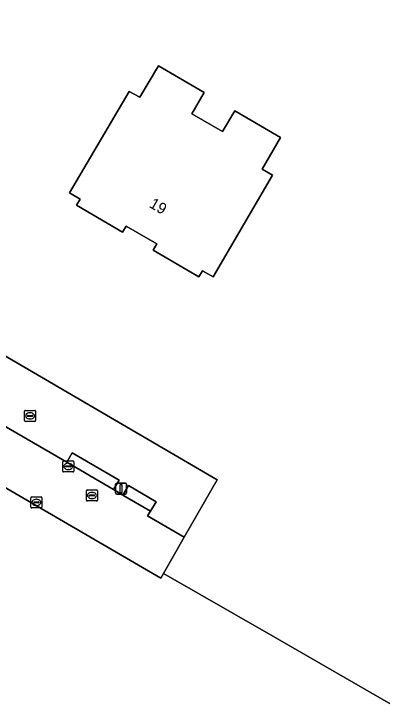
# Model space of a CAD drawing. Extents: x 156502 to 159075, y 384229 to 386100.
# Drawn here: x 157237.2 to 157270.5, y 385820 to 385882.9 of the extents above; entities that cross this region are included whole.
import ezdxf

# ---------------------------------------------------------------- set-up
doc = ezdxf.new("R2010")
doc.units = 0
for name, color, linetype in [('IMGEO_Erf', 7, 'Continuous'), ('IMGEO_Grasland_overig', 7, 'Continuous'), ('IMGEO_Groenvoorziening', 7, 'Continuous'), ('IMGEO_Haag', 7, 'Continuous'), ('IMGEO_Hek', 7, 'Continuous'), ('IMGEO_Kolk', 7, 'Continuous'), ('IMGEO_Lichtmast', 7, 'Continuous'), ('IMGEO_Pand', 7, 'Continuous'), ('IMGEO_Pand_nummerreeks', 7, 'Continuous'), ('IMGEO_Rijbaan_lokaal_open', 7, 'Continuous'), ('IMGEO_Rioolput', 7, 'Continuous'), ('IMGEO_Voetpad_open', 7, 'Continuous')]:
    doc.layers.add(name, color=color, linetype=linetype)

msp = doc.modelspace()

# ---------------------------------------------------------------- linework, layer by layer
at = {"layer": 'IMGEO_Erf'}
msp.add_lwpolyline([(157242.826, 385865.609), (157243.156, 385866.162), (157242.212, 385866.726), (157247.585, 385875.898), (157248.555, 385875.375), (157250.234, 385878.2), (157254.372, 385875.786), (157253.258, 385873.877), (157256.043, 385872.253), (157257.148, 385874.146), (157261.288, 385871.729), (157259.62, 385868.87), (157260.57, 385868.316), (157255.182, 385859.122), (157254.232, 385859.683), (157253.898, 385859.114), (157249.757, 385861.548), (157250.086, 385862.113), (157247.316, 385863.723), (157246.981, 385863.155)], close=True, dxfattribs=at)
msp.add_lwpolyline([(157226.078, 385857.975), (157255.558, 385840.78), (157252.582, 385835.588), (157250.702, 385832.309), (157260.436, 385826.723), (157272.043, 385820.045)], dxfattribs=at)
at = {"layer": 'IMGEO_Grasland_overig'}
msp.add_lwpolyline([(157272.043, 385820.045), (157260.436, 385826.723), (157250.702, 385832.309), (157250.457, 385831.882), (157205.703, 385857.935)], dxfattribs=at)
at = {"layer": 'IMGEO_Groenvoorziening'}
for points in [[(157242.451, 385843.218), (157241.947, 385842.373), (157246.178, 385839.897), (157246.682, 385840.755)], [(157247.026, 385839.395), (157249.511, 385837.937), (157250.029, 385838.788), (157247.532, 385840.247)]]:
    msp.add_lwpolyline(points, close=True, dxfattribs=at)
at = {"layer": 'IMGEO_Haag'}
for points in [[(157242.451, 385843.218), (157241.947, 385842.373), (157246.178, 385839.897), (157246.682, 385840.755)], [(157247.026, 385839.395), (157249.511, 385837.937), (157250.029, 385838.788), (157247.532, 385840.247)]]:
    msp.add_lwpolyline(points, close=True, dxfattribs=at)
at = {"layer": 'IMGEO_Hek'}
for points in [[(157250.457, 385831.882), (157250.702, 385832.309)], [(157260.436, 385826.723), (157250.702, 385832.309)], [(157260.436, 385826.723), (157272.043, 385820.045)]]:
    msp.add_lwpolyline(points, dxfattribs=at)
at = {"layer": 'IMGEO_Kolk'}
for p, q in [((157241.584, 385841.563), (157241.584, 385842.415)), ((157241.659, 385842.489), (157242.511, 385842.489)), ((157242.585, 385842.415), (157242.585, 385841.563)), ((157241.843, 385841.983), (157241.843, 385841.995)), ((157242.281, 385841.946), (157241.883, 385841.946)), ((157241.886, 385842.032), (157242.284, 385842.032)), ((157242.095, 385841.709), (157242.07, 385841.709)), ((157242.072, 385842.269), (157242.097, 385842.269)), ((157242.327, 385841.995), (157242.327, 385841.983)), ((157242.511, 385841.489), (157241.659, 385841.489)), ((157238.781, 385839.233), (157239.633, 385839.233)), ((157238.706, 385838.307), (157238.706, 385839.159)), ((157238.965, 385838.727), (157238.965, 385838.739)), ((157239.403, 385838.69), (157239.005, 385838.69)), ((157239.008, 385838.776), (157239.406, 385838.776)), ((157239.194, 385839.013), (157239.219, 385839.013)), ((157239.449, 385838.739), (157239.449, 385838.727)), ((157239.707, 385839.159), (157239.707, 385838.307)), ((157239.633, 385838.233), (157238.781, 385838.233)), ((157239.217, 385838.453), (157239.192, 385838.453))]:
    msp.add_line(p, q, dxfattribs=at)
for points in [[(157241.584, 385841.563), (157241.584, 385842.415)], [(157241.659, 385842.489), (157242.511, 385842.489)], [(157242.585, 385842.415), (157242.585, 385841.563)], [(157242.511, 385841.489), (157241.659, 385841.489)], [(157238.781, 385839.233), (157239.633, 385839.233)], [(157238.706, 385838.307), (157238.706, 385839.159)], [(157239.707, 385839.159), (157239.707, 385838.307)], [(157239.633, 385838.233), (157238.781, 385838.233)]]:
    msp.add_lwpolyline(points, dxfattribs=at)
for centre, radius, start, end in [((157241.661, 385842.413), 0.0765, 91.55205, 178.44795), ((157241.661, 385842.413), 0.0765, 91.55205, 178.44795), ((157242.509, 385842.413), 0.0765, 1.55205, 88.44795), ((157242.509, 385842.413), 0.0765, 1.55205, 88.44795), ((157241.883, 385841.992), 0.0403, 85.87752, 175.75265), ((157241.88, 385841.982), 0.0366, 178.93798, 274.71019), ((157242.284, 385841.989), 0.043, 264.86636, 352.45326), ((157242.288, 385841.994), 0.0386, 1.73085, 96.63898), ((157241.661, 385841.565), 0.0765, 181.55205, 268.44795), ((157241.661, 385841.565), 0.0765, 181.55205, 268.44795), ((157242.509, 385841.565), 0.0765, 271.55205, 358.44795), ((157242.509, 385841.565), 0.0765, 271.55205, 358.44795), ((157238.783, 385839.157), 0.0765, 91.55205, 178.44795), ((157238.783, 385839.157), 0.0765, 91.55205, 178.44795), ((157239.631, 385839.157), 0.0765, 1.55205, 88.44795), ((157239.631, 385839.157), 0.0765, 1.55205, 88.44795), ((157239.005, 385838.736), 0.0403, 85.87752, 175.75265), ((157239.002, 385838.726), 0.0366, 178.93798, 274.71019), ((157239.406, 385838.733), 0.043, 264.86636, 352.45326), ((157239.41, 385838.738), 0.0386, 1.73085, 96.63898), ((157238.783, 385838.309), 0.0765, 181.55205, 268.44795), ((157238.783, 385838.309), 0.0765, 181.55205, 268.44795), ((157239.631, 385838.309), 0.0765, 271.55205, 358.44795), ((157239.631, 385838.309), 0.0765, 271.55205, 358.44795)]:
    msp.add_arc(centre, radius, start, end, dxfattribs=at)
for centre, major_axis, ratio, start_param, end_param in [((157242.071, 385841.989), (-0.387, 0.002), 0.722429, 4.712389, 7.853982), ((157242.096, 385841.989), (-0.39, 0.002), 0.717154, 1.570796, 4.712389), ((157239.193, 385838.733), (-0.387, 0.002), 0.722429, 4.712389, 7.853982), ((157239.218, 385838.733), (-0.39, 0.002), 0.717154, 1.570796, 4.712389)]:
    msp.add_ellipse(centre, major_axis=major_axis, ratio=ratio, start_param=start_param, end_param=end_param, dxfattribs=at)
at = {"layer": 'IMGEO_Lichtmast'}
for p, q in [((157246.466, 385840.484), (157247.256, 385840.484)), ((157247.256, 385840.484), (157246.466, 385840.484)), ((157246.366, 385839.584), (157246.366, 385840.384)), ((157246.366, 385840.384), (157246.366, 385839.584)), ((157247.356, 385840.384), (157247.356, 385839.584)), ((157247.356, 385839.584), (157247.356, 385840.384)), ((157247.256, 385839.484), (157246.466, 385839.484)), ((157246.466, 385839.484), (157247.256, 385839.484))]:
    msp.add_line(p, q, dxfattribs=at)
msp.add_lwpolyline([(157246.786, 385840.359), (157246.936, 385840.359), (157246.936, 385839.609), (157246.786, 385839.609), (157246.786, 385840.359)], dxfattribs=at)
for centre, start, end in [((157246.466, 385840.384), 90, 180), ((157246.466, 385840.384), 90, 180), ((157247.256, 385840.384), 0, 90), ((157247.256, 385840.384), 360, 90), ((157246.466, 385839.584), 180, 270), ((157246.466, 385839.584), 180, 270), ((157247.256, 385839.584), 270, 0), ((157247.256, 385839.584), 270, 0)]:
    msp.add_arc(centre, 0.1, start, end, dxfattribs=at)
at = {"layer": 'IMGEO_Pand'}
msp.add_lwpolyline([(157253.898, 385859.114), (157254.232, 385859.683), (157255.182, 385859.122), (157260.57, 385868.316), (157259.62, 385868.87), (157261.288, 385871.729), (157257.148, 385874.146), (157256.043, 385872.253), (157253.258, 385873.877), (157254.372, 385875.786), (157250.234, 385878.2), (157248.555, 385875.375), (157247.585, 385875.898), (157242.212, 385866.726), (157243.156, 385866.162), (157242.826, 385865.609), (157246.981, 385863.155), (157247.316, 385863.723), (157250.086, 385862.113), (157249.757, 385861.548)], close=True, dxfattribs=at)
at = {"layer": 'IMGEO_Rijbaan_lokaal_open'}
msp.add_lwpolyline([(157205.703, 385857.935), (157250.457, 385831.882), (157250.702, 385832.309), (157252.582, 385835.588), (157249.263, 385837.527), (157249.511, 385837.937), (157247.026, 385839.395), (157246.178, 385839.897), (157241.947, 385842.373), (157235.934, 385845.88), (157226.506, 385851.343), (157225.619, 385851.871), (157222.254, 385853.823), (157216.161, 385857.317), (157205.901, 385863.335), (157205.084, 385863.813), (157201.692, 385865.761), (157193.644, 385870.453), (157185.088, 385875.436), (157184.271, 385875.92), (157179.189, 385878.901), (157172.275, 385882.9)], dxfattribs=at)
at = {"layer": 'IMGEO_Rioolput'}
for p, q in [((157238.138, 385846.129), (157238.138, 385846.981)), ((157238.213, 385847.055), (157239.065, 385847.055)), ((157238.626, 385846.835), (157238.651, 385846.835)), ((157239.139, 385846.981), (157239.139, 385846.129)), ((157238.397, 385846.549), (157238.397, 385846.561)), ((157238.835, 385846.512), (157238.437, 385846.512)), ((157238.44, 385846.598), (157238.838, 385846.598)), ((157238.649, 385846.275), (157238.624, 385846.275)), ((157238.881, 385846.561), (157238.881, 385846.549)), ((157239.065, 385846.055), (157238.213, 385846.055)), ((157243.803, 385839.86), (157244.655, 385839.86)), ((157243.728, 385838.934), (157243.728, 385839.786)), ((157243.987, 385839.354), (157243.987, 385839.366)), ((157244.425, 385839.317), (157244.027, 385839.317)), ((157244.03, 385839.403), (157244.428, 385839.403)), ((157244.216, 385839.64), (157244.241, 385839.64)), ((157244.471, 385839.366), (157244.471, 385839.354)), ((157244.729, 385839.786), (157244.729, 385838.934)), ((157244.655, 385838.86), (157243.803, 385838.86)), ((157244.239, 385839.08), (157244.214, 385839.08))]:
    msp.add_line(p, q, dxfattribs=at)
for points in [[(157238.138, 385846.129), (157238.138, 385846.981)], [(157238.213, 385847.055), (157239.065, 385847.055)], [(157239.139, 385846.981), (157239.139, 385846.129)], [(157239.065, 385846.055), (157238.213, 385846.055)], [(157243.803, 385839.86), (157244.655, 385839.86)], [(157243.728, 385838.934), (157243.728, 385839.786)], [(157244.729, 385839.786), (157244.729, 385838.934)], [(157244.655, 385838.86), (157243.803, 385838.86)]]:
    msp.add_lwpolyline(points, dxfattribs=at)
for centre, radius, start, end in [((157238.215, 385846.979), 0.0765, 91.55205, 178.44795), ((157238.215, 385846.979), 0.0765, 91.55205, 178.44795), ((157239.063, 385846.979), 0.0765, 1.55205, 88.44795), ((157239.063, 385846.979), 0.0765, 1.55205, 88.44795), ((157238.215, 385846.131), 0.0765, 181.55205, 268.44795), ((157238.215, 385846.131), 0.0765, 181.55205, 268.44795), ((157238.437, 385846.558), 0.0403, 85.87752, 175.75265), ((157238.434, 385846.548), 0.0366, 178.93798, 274.71019), ((157238.838, 385846.555), 0.043, 264.86636, 352.45326), ((157238.842, 385846.56), 0.0386, 1.73085, 96.63898), ((157239.063, 385846.131), 0.0765, 271.55205, 358.44795), ((157239.063, 385846.131), 0.0765, 271.55205, 358.44795), ((157243.805, 385839.784), 0.0765, 91.55205, 178.44795), ((157243.805, 385839.784), 0.0765, 91.55205, 178.44795), ((157244.653, 385839.784), 0.0765, 1.55205, 88.44795), ((157244.653, 385839.784), 0.0765, 1.55205, 88.44795), ((157244.027, 385839.363), 0.0403, 85.87752, 175.75265), ((157244.024, 385839.353), 0.0366, 178.93798, 274.71019), ((157244.428, 385839.36), 0.043, 264.86636, 352.45326), ((157244.432, 385839.365), 0.0386, 1.73085, 96.63898), ((157243.805, 385838.936), 0.0765, 181.55205, 268.44795), ((157243.805, 385838.936), 0.0765, 181.55205, 268.44795), ((157244.653, 385838.936), 0.0765, 271.55205, 358.44795), ((157244.653, 385838.936), 0.0765, 271.55205, 358.44795)]:
    msp.add_arc(centre, radius, start, end, dxfattribs=at)
for centre, major_axis, ratio, start_param, end_param in [((157238.625, 385846.555), (-0.387, 0.002), 0.722429, 4.712389, 7.853982), ((157238.65, 385846.555), (-0.39, 0.002), 0.717154, 1.570796, 4.712389), ((157244.215, 385839.36), (-0.387, 0.002), 0.722429, 4.712389, 7.853982), ((157244.24, 385839.36), (-0.39, 0.002), 0.717154, 1.570796, 4.712389)]:
    msp.add_ellipse(centre, major_axis=major_axis, ratio=ratio, start_param=start_param, end_param=end_param, dxfattribs=at)
at = {"layer": 'IMGEO_Voetpad_open'}
msp.add_lwpolyline([(157235.934, 385845.88), (157241.947, 385842.373), (157242.451, 385843.218), (157246.682, 385840.755), (157246.178, 385839.897), (157247.026, 385839.395), (157247.532, 385840.247), (157250.029, 385838.788), (157249.511, 385837.937), (157249.263, 385837.527), (157252.582, 385835.588), (157255.558, 385840.78), (157226.078, 385857.975)], dxfattribs=at)

# ---------------------------------------------------------------- texts
at = {"layer": 'IMGEO_Pand_nummerreeks'}
msp.add_text('19', height=1, rotation=329.82783, dxfattribs=at).set_placement((157249.332, 385865.466))

doc.saveas('drawing.dxf')
